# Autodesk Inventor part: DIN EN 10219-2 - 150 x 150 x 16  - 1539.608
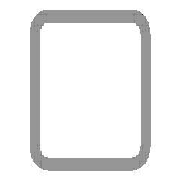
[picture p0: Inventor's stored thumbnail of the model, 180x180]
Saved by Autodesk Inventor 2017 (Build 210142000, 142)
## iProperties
Created: 2017-11
Part Number: DIN EN 10219-2 - 150 x 150 x 16  - 1539.608
Material: Steel, Mild
Description: Cold formed welded structural hollow sections of non-alloy and fine grain structural steel
Document SubType Name: Modeling
Standard: DIN
Designer: iusti
Standard Revision: 2006-07
Standards Organization: DIN
Language: en-US
Size Designation: 150 x 150 x 16
Categories: <MemberInstance><Categories><Category DisplayName="Structural Shapes" InternalName="089c4875-fa83-4c05-b084-43b9cc11f5ed" Mnemonic="GRDR"><CategoryParameter Dis
Stock Number: 150 x 150 x 16
Mass: 90369.3 g
Surface Area: 14539.6 cm^2
Volume: 11512 cm^3
Density: 7.85 g/cm^3
Appearance: Semi-Polished
IsCustomPart: 1
G_W: 150.000 mm
G_H: 150.000 mm
G_L: 1539.608 mm
+A2D54500-A6BB-4D6E-934F-4456235B9375+CUTDETAIL2: Cut
_CCFamilyMember: 76
_CCFamilyDisplayName: DIN EN 10219-2 (Square Hollow Section - Cold Formed) - Cold formed welded structural hollow sections of non-alloy and fine grain structural steel
_FrameMemberDoc: Frame Member File
_Version: 15.0.0
_GetPNFromCC: 1
Author: iusti
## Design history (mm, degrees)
node "Start plane"
node "End plane"
sketch "Sketch"
  geometry: L1 (-75, -27)-(-75, 27); L2 (-27, 75)-(27, 75); L3 (75, 27)-(75, -27); L4 (27, -75)-(-27, -75); L5 (-27, 59)-(27, 59); L6 (59, 27)-(59, -27); L7 (27, -59)-(-27, -59); L8 (-59, -27)-(-59, 27); L9 (0, 118.918)-(0, -118.918) reference; L10 (-118.918, 0)-(118.918, 0) reference; A1 r 48 centre (-27, -27) between (-75, -27) and (-27, -75); A2 r 48 centre (-27, 27) between (-27, 75) and (-75, 27); A3 r 48 centre (27, 27) between (75, 27) and (27, 75); A4 r 48 centre (27, -27) between (27, -75) and (75, -27); A5 r 32 centre (-27, 27) between (-27, 59) and (-59, 27); A6 r 32 centre (27, 27) between (59, 27) and (27, 59); A7 r 32 centre (27, -27) between (27, -59) and (59, -27); A8 r 32 centre (-27, -27) between (-59, -27) and (-27, -59)
  constraints: 16 end point, 16 point on circle, 8 centre point, 8 tangent, 4 parallel, 3 equal radius, 2 perpendicular, 7 other
  dimensions: "d7" = 48 radius of A1 (= G_IR); "d10" = 150 distance between parallel lines of L2 L4 (= G_H); "d11" = 150 distance between parallel lines of L1 L3 (= G_W); "d12" = 16 distance between parallel lines of L3 L6 (= G_T); "d15" = 75 distance between parallel lines of L2 L10 (= 0.5 x d10); "d16" = 75 distance between parallel lines of L9 L3 (= 0.5 x d11)
extrude "Body" new body sketch "Sketch" stored distance "d3" = 1539.60835 (= G_L); taper "d4" = 0 deg
node "Driven Length"
  sketch "Sketch3"
    geometry: L1 (0, 0)-(10, 0) reference
    constraints: 2 end point, 1 horizontal
  workplane "Work Plane3"
  sketch "Sketch4"
    geometry: L1 (-2, 0)-(12, 0) reference; L2 (-2, 1539.608)-(12, 1539.608) reference
    dimensions: "d18" = 1539.60835 distance between parallel lines of L1 L2 (derived)
workplane "Work Plane5"
split "Split2"
body "Solid1"
other parameters: "G_W" = 150 [user parameter; used in 1 equation term], "G_H" = 150 [user parameter; used in 1 equation term], "G_T" = 16 [user parameter; used in 1 equation term], "G_IR" = 48 [user parameter; used in 1 equation term], "G_L" = 1539.60835 (= d18) [user parameter; used in 1 equation term], "G_OFFSET_START" = 0 [user parameter; used in 1 equation term], "G_OFFSET_END" = -75 [user parameter; used in 1 equation term], "d13" = 0 (computed from G_OFFSET_START), "d14" = 1539.60835 (= G_OFFSET_END + B_L), "B_L" = 1614.60835 [user parameter; used in 1 equation term], "d17" = 90 deg
